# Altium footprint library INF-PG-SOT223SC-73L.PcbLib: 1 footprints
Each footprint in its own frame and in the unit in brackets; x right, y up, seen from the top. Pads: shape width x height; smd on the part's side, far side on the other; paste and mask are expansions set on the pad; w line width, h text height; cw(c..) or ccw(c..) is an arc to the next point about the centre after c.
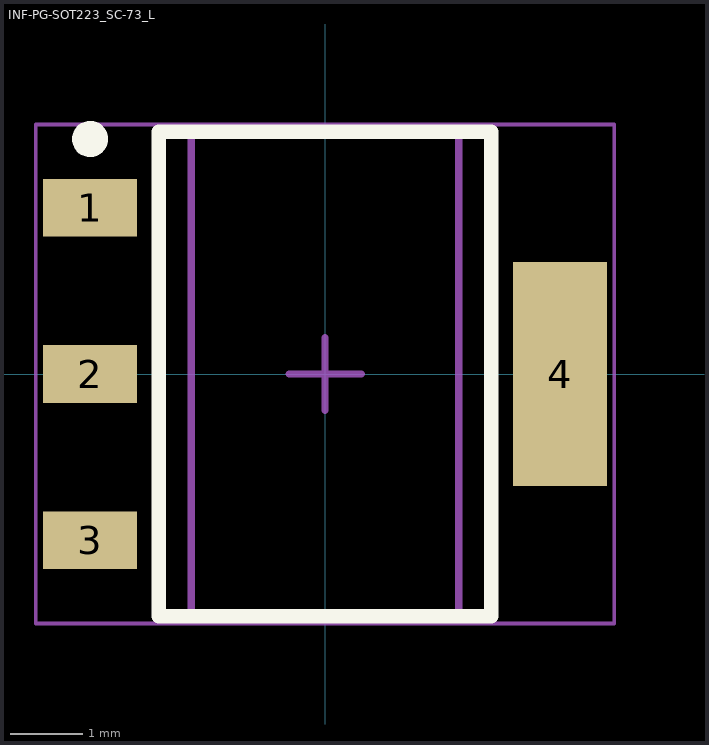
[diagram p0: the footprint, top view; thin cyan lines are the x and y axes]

## INF-PG-SOT223_SC-73_L [mm] "SOT223, 4-Leads, Body 6.5x3.5mm, Pitch 2.3mm, IPC High Density"
height 1.8
pads (4):
  rect 1.3x0.8 smd: 1(-3.25,2.3) 2(-3.25,0) 3(-3.25,-2.3)
  rect 1.3x3.1 smd: 4(3.25,0)
Top Overlay:
  circle w0.25: c-3.25,3.25 r0.125
  lines w0.2: -2.3,-3.35 2.3,-3.35 2.3,3.35 -2.3,3.35 -2.3,-3.35
Mechanical 13:
  lines w0.1: -1.85,-3.35 1.85,-3.35 1.85,3.35 -1.85,3.35 -1.85,-3.35
Mechanical 15:
  lines w0.05: -4,-3.45 4,-3.45 4,3.45 -4,3.45 -4,-3.45
  lines w0.1: -0.5,0 0.5,0 ; 0,-0.5 0,0.5
3D body: height 1.8, standoff 0.1, extent -1.85,-3.35 1.85,3.35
